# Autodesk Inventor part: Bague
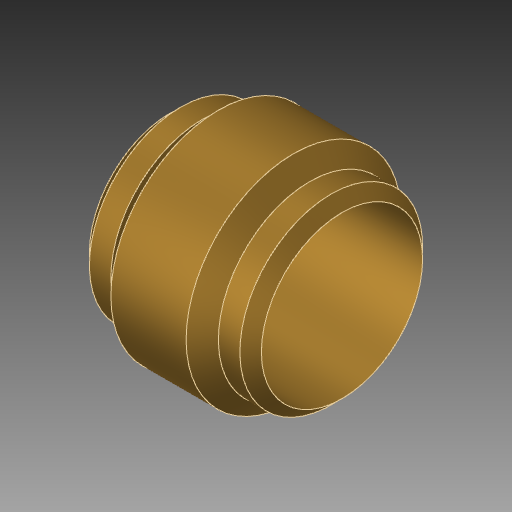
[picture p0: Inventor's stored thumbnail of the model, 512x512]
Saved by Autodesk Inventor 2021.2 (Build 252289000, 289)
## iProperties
Created: 2018-06
Part Number: Bague
Material: Laiton, jaune doux
Document SubType Name: Modeling
Designer: Fabian Perrée
Density: 8.47 g/cm^3
Appearance: Laiton - Satiné
Mass: 1.57799 g
Surface Area: 4.49046 cm^2
Volume: 0.186303 cm^3
Author: Fabian Perrée
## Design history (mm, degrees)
sketch "Esquisse1"
  geometry: L1 (0, 0)-(8, 0); L2 (0, 3.75)-(8, 3.75); L3 (4, 0)-(4, 10.788); L4 (8, 3.75)-(8, 3.75); L5 (7.5, 4.25)-(6.5, 4.25); L6 (6.5, 4.25)-(6.5, 4.25); L7 (5.75, 5)-(2.25, 5); L8 (1.5, 4.25)-(1.5, 4.25); L9 (1.5, 4.25)-(0.5, 4.25); L10 (0, 3.75)-(0, 3.75); L11 (1.5, 4.25)-(2.25, 5); L12 (5.75, 5)-(6.5, 4.25); L13 (0.5, 4.25)-(0, 3.75); L14 (7.5, 4.25)-(8, 3.75); 4 further points
  constraints: 28 end point, 10 point on line, 5 perpendicular, 2 horizontal, 2 vertical, 2 vertical alignment, 1 midpoint, 1 other
  dimensions: "d0" = 8 distance of L2.start L2.end; "d2" = 7.5 diameter of L2 L1; "d3" = 8.5 diameter of L5 L1; "d4" = 10 diameter of L7 L1; "d6" = 0.75 distance of L8.start point (1.5, 5); "d7" = 0.75 distance of L7.end point (1.5, 5) (= d6); "d8" = 0.75 distance of L7.start point (6.5, 5) (= d6); "d9" = 0.75 distance of L6.end point (6.5, 5) (= d8); "d10" = 0.5 distance of L9.end point (0, 4.25); "d11" = 0.5 distance of L10.start point (0, 4.25) (= d10); "d12" = 0.5 distance of L5.start point (8, 4.25) (= d10); "d13" = 0.5 distance of L4.end point (8, 4.25) (= d12); "d14" = 3.5 distance of L7.start L7.end
revolve "Révolution1" sketch "Esquisse1" stored, may be unused: angle "d5" = 90 deg
node "Solide1"
